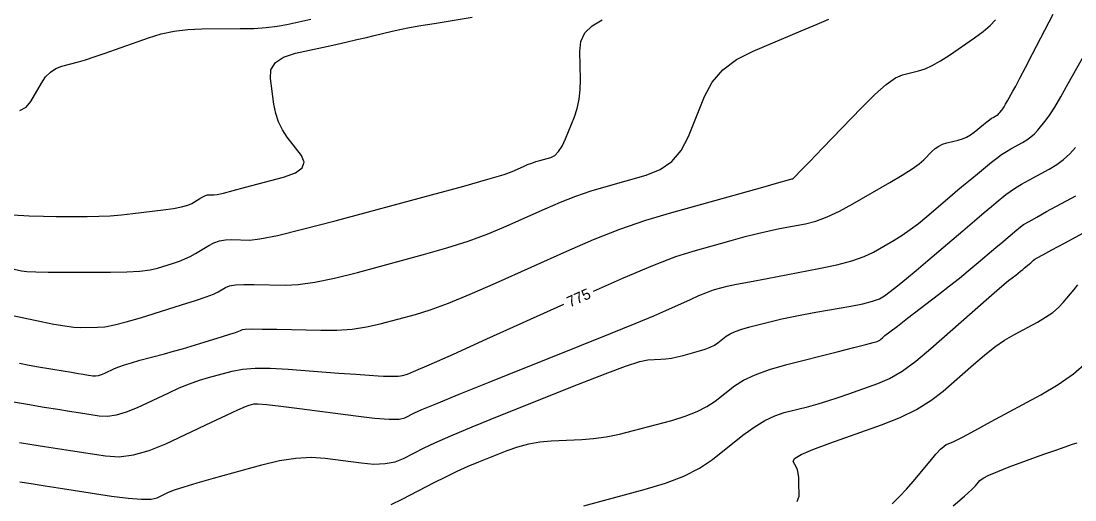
# Model space of a CAD drawing. Extents: x 2082232 to 2083549, y 592624 to 593832.
# Drawn here: x 2082483.9 to 2082552.2, y 592949.4 to 592980.4 of the extents above; entities that cross this region are included whole.
import ezdxf

# ---------------------------------------------------------------- set-up
doc = ezdxf.new("R2010")
doc.units = 0
doc.layers.add('DT_X_Contour_Major', color=7, linetype='Continuous')
doc.layers.add('DT_X_Contour_Minor', color=7, linetype='Continuous')

msp = doc.modelspace()

# ---------------------------------------------------------------- linework, layer by layer
at = {"layer": 'DT_X_Contour_Major'}
for points in [[(2082483.872, 592974.624), (2082484.273, 592974.838), (2082484.577, 592975.206), (2082485.26, 592976.391), (2082485.535, 592976.793), (2082485.847, 592977.111), (2082486.196, 592977.345), (2082486.583, 592977.495), (2082487.664, 592977.782), (2082488.119, 592977.912), (2082488.672, 592978.086), (2082489.323, 592978.306), (2082490.072, 592978.57), (2082492.2, 592979.333), (2082493.014, 592979.584), (2082493.862, 592979.764), (2082494.743, 592979.874), (2082495.656, 592979.913), (2082498.137, 592979.922), (2082499.024, 592979.941), (2082499.824, 592979.991), (2082500.536, 592980.072), (2082501.161, 592980.185), (2082502.711, 592980.528)], [(2082521.028, 592962.923), (2082522.974, 592963.782), (2082524.862, 592964.573), (2082526.365, 592965.151), (2082527.484, 592965.516), (2082529.955, 592966.206), (2082530.845, 592966.448), (2082531.661, 592966.654), (2082532.405, 592966.826), (2082533.075, 592966.964), (2082534.764, 592967.284), (2082535.431, 592967.454), (2082536.163, 592967.724), (2082536.962, 592968.095), (2082537.827, 592968.567), (2082540.221, 592969.958), (2082541.032, 592970.44), (2082541.668, 592970.844), (2082542.13, 592971.169), (2082542.418, 592971.416), (2082542.953, 592971.971), (2082543.163, 592972.161), (2082543.393, 592972.316), (2082543.643, 592972.436), (2082543.913, 592972.52), (2082544.659, 592972.698), (2082544.933, 592972.78), (2082545.195, 592972.893), (2082545.444, 592973.037), (2082545.682, 592973.211), (2082546.3, 592973.718), (2082546.512, 592973.889), (2082546.683, 592974.023), (2082546.815, 592974.119), (2082546.907, 592974.176), (2082547.099, 592974.28), (2082547.169, 592974.322), (2082547.233, 592974.37), (2082547.292, 592974.423), (2082547.346, 592974.482), (2082547.482, 592974.647), (2082547.543, 592974.731), (2082547.624, 592974.858), (2082547.725, 592975.028), (2082547.846, 592975.242), (2082548.197, 592975.869), (2082548.374, 592976.196), (2082548.644, 592976.707), (2082549.006, 592977.402), (2082549.461, 592978.28), (2082550.797, 592980.867)], [(2082534.209, 592949.29), (2082534.347, 592949.627), (2082534.336, 592950.533), (2082534.323, 592950.848), (2082534.291, 592951.115), (2082534.241, 592951.332), (2082534.172, 592951.501), (2082533.964, 592951.885), (2082534.053, 592952.067), (2082534.477, 592952.325), (2082535.235, 592952.658), (2082536.328, 592953.066), (2082539.688, 592954.257), (2082540.883, 592954.729), (2082541.946, 592955.251), (2082542.877, 592955.823), (2082543.678, 592956.446), (2082545.637, 592958.174), (2082546.352, 592958.779), (2082547.026, 592959.3), (2082547.659, 592959.737), (2082548.253, 592960.089), (2082549.781, 592960.916), (2082550.315, 592961.227), (2082550.772, 592961.54), (2082551.151, 592961.854), (2082551.453, 592962.171), (2082552.155, 592963.017), (2082552.411, 592963.315)], [(2082481.33, 592956.093), (2082484.373, 592955.585), (2082485.435, 592955.409), (2082486.337, 592955.26), (2082487.08, 592955.14), (2082487.663, 592955.048), (2082489.006, 592954.841), (2082489.539, 592954.816), (2082490.131, 592954.899), (2082490.783, 592955.088), (2082491.494, 592955.384), (2082493.469, 592956.317), (2082494.189, 592956.642), (2082494.867, 592956.918), (2082495.503, 592957.145), (2082496.098, 592957.323), (2082497.629, 592957.733), (2082498.286, 592957.856), (2082499.107, 592957.917), (2082500.092, 592957.917), (2082501.243, 592957.855), (2082504.53, 592957.61), (2082505.635, 592957.529), (2082506.486, 592957.469), (2082507.083, 592957.432), (2082507.426, 592957.416), (2082508.002, 592957.403), (2082508.205, 592957.403), (2082508.382, 592957.411), (2082508.535, 592957.429), (2082508.662, 592957.455), (2082508.968, 592957.538), (2082509.377, 592957.703), (2082510.373, 592958.139), (2082511.957, 592958.844), (2082514.128, 592959.819), (2082519.112, 592962.063)]]:
    msp.add_lwpolyline(points, dxfattribs=at)
at = {"layer": 'DT_X_Contour_Minor'}
for points in [[(2082482.89, 592961.449), (2082485.251, 592960.945), (2082486.075, 592960.78), (2082486.779, 592960.662), (2082487.361, 592960.592), (2082487.822, 592960.57), (2082488.891, 592960.574), (2082489.366, 592960.614), (2082489.99, 592960.731), (2082490.764, 592960.924), (2082491.686, 592961.195), (2082494.345, 592962.019), (2082495.241, 592962.303), (2082495.933, 592962.538), (2082496.421, 592962.724), (2082496.706, 592962.861), (2082497.195, 592963.159), (2082497.449, 592963.255), (2082497.843, 592963.318), (2082498.379, 592963.35), (2082499.056, 592963.349), (2082501.049, 592963.305), (2082501.903, 592963.344), (2082502.97, 592963.495), (2082504.25, 592963.759), (2082505.744, 592964.134), (2082510.011, 592965.285), (2082511.537, 592965.719), (2082512.913, 592966.158), (2082514.14, 592966.602), (2082515.218, 592967.051), (2082517.893, 592968.255), (2082518.892, 592968.685), (2082519.884, 592969.069), (2082520.867, 592969.408), (2082521.844, 592969.702), (2082524.436, 592970.426), (2082525.336, 592970.786), (2082526.092, 592971.322), (2082526.704, 592972.036), (2082527.171, 592972.926), (2082528.225, 592975.536), (2082528.718, 592976.454), (2082529.404, 592977.248), (2082530.285, 592977.92), (2082531.36, 592978.47), (2082534.486, 592979.771), (2082535.519, 592980.205), (2082536.272, 592980.532)], [(2082483.305, 592964.381), (2082483.966, 592964.24), (2082484.324, 592964.194), (2082484.904, 592964.162), (2082485.705, 592964.145), (2082486.728, 592964.142), (2082489.749, 592964.154), (2082490.789, 592964.173), (2082491.643, 592964.22), (2082492.31, 592964.297), (2082492.79, 592964.402), (2082493.822, 592964.722), (2082494.202, 592964.852), (2082494.564, 592965.001), (2082494.911, 592965.169), (2082495.241, 592965.356), (2082496.101, 592965.881), (2082496.436, 592966.051), (2082496.798, 592966.171), (2082497.187, 592966.239), (2082497.601, 592966.255), (2082498.743, 592966.229), (2082499.41, 592966.3), (2082500.556, 592966.531), (2082502.181, 592966.922), (2082504.285, 592967.474), (2082510.533, 592969.158), (2082512.617, 592969.726), (2082514.183, 592970.167), (2082515.232, 592970.481), (2082515.763, 592970.667), (2082516.489, 592970.994), (2082516.76, 592971.11), (2082517.029, 592971.214), (2082517.296, 592971.306), (2082517.561, 592971.386), (2082518.264, 592971.583), (2082518.522, 592971.713), (2082518.767, 592971.958), (2082519, 592972.318), (2082519.221, 592972.791), (2082519.792, 592974.206), (2082519.977, 592974.755), (2082520.104, 592975.343), (2082520.172, 592975.968), (2082520.182, 592976.631), (2082520.131, 592978.45), (2082520.207, 592979.088), (2082520.474, 592979.64), (2082520.931, 592980.105), (2082521.578, 592980.484)], [(2082483.41, 592967.861), (2082484.472, 592967.8), (2082485.409, 592967.765), (2082486.223, 592967.754), (2082488.227, 592967.758), (2082488.976, 592967.771), (2082489.72, 592967.805), (2082490.459, 592967.862), (2082491.194, 592967.941), (2082493.146, 592968.18), (2082493.811, 592968.274), (2082494.343, 592968.375), (2082494.741, 592968.484), (2082495.006, 592968.601), (2082495.534, 592968.924), (2082495.721, 592969.029), (2082495.885, 592969.104), (2082496.027, 592969.147), (2082496.147, 592969.16), (2082496.437, 592969.154), (2082496.647, 592969.183), (2082497.06, 592969.274), (2082497.676, 592969.429), (2082498.495, 592969.646), (2082500.951, 592970.308), (2082501.713, 592970.581), (2082502.16, 592970.904), (2082502.29, 592971.277), (2082502.103, 592971.7), (2082501.184, 592972.894), (2082500.872, 592973.363), (2082500.624, 592973.876), (2082500.442, 592974.432), (2082500.324, 592975.031), (2082500.096, 592976.687), (2082500.134, 592977.255), (2082500.419, 592977.718), (2082500.951, 592978.076), (2082501.729, 592978.328), (2082504.134, 592978.859), (2082504.978, 592979.047), (2082505.706, 592979.211), (2082506.318, 592979.353), (2082506.814, 592979.471), (2082507.984, 592979.756), (2082508.483, 592979.868), (2082509.102, 592979.99), (2082509.842, 592980.122), (2082510.703, 592980.264), (2082513.159, 592980.658)], [(2082483.836, 592958.241), (2082484.461, 592958.125), (2082485.07, 592958.019), (2082486.67, 592957.752), (2082487.215, 592957.662), (2082487.649, 592957.59), (2082487.973, 592957.537), (2082488.185, 592957.504), (2082488.603, 592957.439), (2082488.77, 592957.431), (2082488.954, 592957.457), (2082489.158, 592957.516), (2082489.379, 592957.608), (2082489.995, 592957.899), (2082490.271, 592958.014), (2082490.639, 592958.142), (2082491.097, 592958.282), (2082491.647, 592958.435), (2082493.233, 592958.859), (2082493.823, 592959.02), (2082494.4, 592959.183), (2082494.966, 592959.349), (2082495.521, 592959.518), (2082496.985, 592959.971), (2082497.47, 592960.124), (2082497.83, 592960.24), (2082498.063, 592960.321), (2082498.171, 592960.365), (2082498.289, 592960.437), (2082498.461, 592960.458), (2082498.888, 592960.466), (2082499.572, 592960.461), (2082500.51, 592960.444), (2082503.355, 592960.38), (2082504.395, 592960.388), (2082505.384, 592960.46), (2082506.32, 592960.595), (2082507.203, 592960.795), (2082509.49, 592961.411), (2082510.457, 592961.711), (2082511.643, 592962.148), (2082513.048, 592962.723), (2082514.673, 592963.435), (2082519.297, 592965.517), (2082521.022, 592966.258), (2082522.731, 592966.921), (2082524.422, 592967.504), (2082526.096, 592968.009), (2082530.538, 592969.25), (2082531.997, 592969.657), (2082533.04, 592969.948), (2082533.669, 592970.123), (2082533.883, 592970.182), (2082533.9, 592970.186), (2082533.907, 592970.187), (2082533.914, 592970.19), (2082533.922, 592970.194), (2082533.931, 592970.199), (2082533.955, 592970.213), (2082534.081, 592970.34), (2082534.441, 592970.71), (2082535.035, 592971.325), (2082535.863, 592972.183), (2082538.384, 592974.796), (2082539.259, 592975.665), (2082539.995, 592976.312), (2082540.592, 592976.737), (2082541.05, 592976.94), (2082542.085, 592977.187), (2082542.501, 592977.32), (2082542.973, 592977.535), (2082543.5, 592977.831), (2082544.084, 592978.209), (2082545.714, 592979.325), (2082546.271, 592979.734), (2082546.72, 592980.124), (2082547.059, 592980.495)], [(2082483.853, 592953.121), (2082484.654, 592952.989), (2082485.47, 592952.857), (2082486.299, 592952.725), (2082487.142, 592952.593), (2082489.408, 592952.242), (2082490.291, 592952.193), (2082491.237, 592952.307), (2082492.247, 592952.584), (2082493.322, 592953.025), (2082496.274, 592954.419), (2082497.256, 592954.88), (2082497.991, 592955.219), (2082498.477, 592955.434), (2082498.715, 592955.527), (2082499.018, 592955.611), (2082499.289, 592955.616), (2082499.872, 592955.569), (2082500.769, 592955.468), (2082501.979, 592955.314), (2082505.624, 592954.833), (2082506.848, 592954.69), (2082507.788, 592954.622), (2082508.444, 592954.629), (2082508.815, 592954.711), (2082509.425, 592955.029), (2082509.9, 592955.243), (2082510.868, 592955.648), (2082512.327, 592956.242), (2082514.278, 592957.027), (2082520.137, 592959.374), (2082522.134, 592960.177), (2082523.731, 592960.827), (2082524.926, 592961.325), (2082525.721, 592961.669), (2082527.307, 592962.383), (2082527.851, 592962.624), (2082528.293, 592962.811), (2082528.633, 592962.944), (2082528.871, 592963.023), (2082529.371, 592963.163), (2082529.693, 592963.239), (2082530.283, 592963.361), (2082531.141, 592963.53), (2082532.267, 592963.745), (2082535.628, 592964.382), (2082536.794, 592964.627), (2082537.771, 592964.886), (2082538.559, 592965.159), (2082539.157, 592965.445), (2082540.501, 592966.225), (2082541.012, 592966.541), (2082541.536, 592966.901), (2082542.072, 592967.307), (2082542.622, 592967.758), (2082544.106, 592969.02), (2082544.635, 592969.469), (2082545.111, 592969.87), (2082545.533, 592970.222), (2082545.901, 592970.526), (2082546.81, 592971.272), (2082547.145, 592971.537), (2082547.465, 592971.769), (2082547.771, 592971.971), (2082548.063, 592972.141), (2082548.825, 592972.553), (2082549.1, 592972.719), (2082549.354, 592972.907), (2082549.587, 592973.118), (2082549.8, 592973.352), (2082550.339, 592974.007), (2082550.581, 592974.338), (2082550.903, 592974.841), (2082551.304, 592975.515), (2082551.784, 592976.361), (2082553.171, 592978.846)], [(2082483.874, 592950.569), (2082484.602, 592950.453), (2082485.517, 592950.309), (2082486.62, 592950.138), (2082489.811, 592949.644), (2082490.893, 592949.499), (2082491.745, 592949.432), (2082492.368, 592949.445), (2082492.761, 592949.537), (2082493.504, 592949.888), (2082493.895, 592950.044), (2082494.509, 592950.248), (2082495.348, 592950.501), (2082496.411, 592950.803), (2082499.545, 592951.672), (2082500.683, 592951.943), (2082501.745, 592952.103), (2082502.733, 592952.153), (2082503.646, 592952.093), (2082505.979, 592951.785), (2082506.807, 592951.717), (2082507.541, 592951.742), (2082508.182, 592951.861), (2082508.729, 592952.075), (2082510.061, 592952.769), (2082510.74, 592953.094), (2082511.775, 592953.546), (2082513.167, 592954.126), (2082514.917, 592954.834), (2082520.057, 592956.893), (2082521.784, 592957.57), (2082523.108, 592958.058), (2082524.029, 592958.357), (2082524.548, 592958.467), (2082525.395, 592958.507), (2082525.722, 592958.534), (2082526.07, 592958.584), (2082526.438, 592958.657), (2082526.826, 592958.752), (2082527.888, 592959.039), (2082528.261, 592959.152), (2082528.586, 592959.279), (2082528.862, 592959.419), (2082529.088, 592959.571), (2082529.627, 592959.996), (2082529.874, 592960.153), (2082530.209, 592960.305), (2082530.632, 592960.453), (2082531.143, 592960.597), (2082532.625, 592960.975), (2082533.217, 592961.118), (2082533.883, 592961.261), (2082534.622, 592961.407), (2082535.435, 592961.553), (2082537.7, 592961.945), (2082538.473, 592962.097), (2082539.094, 592962.258), (2082539.563, 592962.429), (2082539.879, 592962.608), (2082540.518, 592963.1), (2082540.834, 592963.351), (2082541.301, 592963.736), (2082541.919, 592964.255), (2082542.689, 592964.907), (2082544.945, 592966.826), (2082545.714, 592967.48), (2082546.332, 592968.003), (2082546.798, 592968.394), (2082547.112, 592968.655), (2082547.746, 592969.175), (2082548.017, 592969.38), (2082548.352, 592969.603), (2082548.753, 592969.845), (2082549.22, 592970.106), (2082550.55, 592970.825), (2082551.031, 592971.115), (2082551.475, 592971.444), (2082551.883, 592971.814), (2082552.254, 592972.223)], [(2082507.92, 592949.094), (2082508.642, 592949.439), (2082510.697, 592950.51), (2082511.457, 592950.895), (2082512.195, 592951.249), (2082512.912, 592951.571), (2082513.607, 592951.861), (2082515.431, 592952.591), (2082516.123, 592952.835), (2082516.829, 592953.02), (2082517.55, 592953.145), (2082518.285, 592953.21), (2082520.266, 592953.304), (2082521.032, 592953.367), (2082521.846, 592953.483), (2082522.707, 592953.653), (2082523.615, 592953.878), (2082526.099, 592954.547), (2082526.973, 592954.814), (2082527.732, 592955.11), (2082528.377, 592955.437), (2082528.908, 592955.794), (2082530.169, 592956.786), (2082530.736, 592957.151), (2082531.49, 592957.5), (2082532.431, 592957.835), (2082533.559, 592958.154), (2082536.818, 592958.985), (2082537.892, 592959.26), (2082538.67, 592959.46), (2082539.152, 592959.585), (2082539.338, 592959.636), (2082539.439, 592959.672), (2082539.479, 592959.689), (2082539.523, 592959.716), (2082539.571, 592959.751), (2082539.623, 592959.794), (2082539.767, 592959.921), (2082539.908, 592960.035), (2082540.222, 592960.28), (2082540.71, 592960.657), (2082541.371, 592961.166), (2082543.366, 592962.698), (2082544.08, 592963.252), (2082544.727, 592963.764), (2082545.307, 592964.234), (2082545.819, 592964.662), (2082547.096, 592965.748), (2082547.532, 592966.118), (2082547.882, 592966.414), (2082548.145, 592966.636), (2082548.323, 592966.784), (2082548.682, 592967.078), (2082548.889, 592967.223), (2082549.24, 592967.437), (2082549.736, 592967.719), (2082550.376, 592968.07), (2082552.275, 592969.098)], [(2082520.403, 592949.003), (2082524.309, 592950.056), (2082525.684, 592950.475), (2082526.879, 592950.941), (2082527.893, 592951.455), (2082528.727, 592952.016), (2082530.711, 592953.577), (2082531.436, 592954.108), (2082532.123, 592954.53), (2082532.773, 592954.845), (2082533.386, 592955.05), (2082534.968, 592955.454), (2082535.576, 592955.618), (2082536.212, 592955.806), (2082536.876, 592956.019), (2082537.567, 592956.257), (2082539.45, 592956.924), (2082540.193, 592957.254), (2082541.011, 592957.742), (2082541.904, 592958.39), (2082542.872, 592959.197), (2082545.551, 592961.56), (2082546.452, 592962.352), (2082547.146, 592962.956), (2082547.632, 592963.372), (2082547.91, 592963.601), (2082548.376, 592963.958), (2082548.543, 592964.088), (2082548.694, 592964.207), (2082548.83, 592964.317), (2082548.949, 592964.417), (2082549.247, 592964.671), (2082549.349, 592964.757), (2082549.431, 592964.826), (2082549.492, 592964.878), (2082549.534, 592964.913), (2082549.618, 592964.981), (2082549.761, 592965.067), (2082550.128, 592965.271), (2082550.718, 592965.593), (2082551.532, 592966.035), (2082554, 592967.37)], [(2082540.367, 592949.146), (2082540.844, 592949.607), (2082541.296, 592950.084), (2082541.724, 592950.575), (2082542.834, 592951.904), (2082543.211, 592952.345), (2082543.511, 592952.671), (2082543.734, 592952.883), (2082543.88, 592952.979), (2082544.166, 592953.083), (2082544.41, 592953.199), (2082544.928, 592953.467), (2082545.72, 592953.889), (2082546.786, 592954.463), (2082549.994, 592956.198), (2082551.126, 592956.864), (2082552.119, 592957.561), (2082552.971, 592958.289)], [(2082544.325, 592948.998), (2082545.053, 592949.636), (2082545.534, 592950.07), (2082545.767, 592950.303), (2082546.058, 592950.651), (2082546.259, 592950.804), (2082546.642, 592951.001), (2082547.209, 592951.242), (2082547.958, 592951.527), (2082550.2, 592952.345), (2082550.966, 592952.622), (2082551.583, 592952.839), (2082552.05, 592952.995), (2082552.367, 592953.092)]]:
    msp.add_lwpolyline(points, dxfattribs=at)

# ---------------------------------------------------------------- texts
at = {"layer": 'DT_X_Contour_Major'}
msp.add_text('775', height=0.7, rotation=24.16943, dxfattribs=at).set_placement((2082519.496, 592961.854))

doc.saveas('drawing.dxf')
